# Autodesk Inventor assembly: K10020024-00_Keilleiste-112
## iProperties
Created: 2006-08
Part Number: K10020024-00_Keilleiste-112
Document SubType Name: Assembly
Designer: Kitscha
SBm.TeileNr: K10020024
SBm.TeileRev: 00
SBm.Rohteil: -
SBm.Werkstoff: -
SBm.WerkstNr: -
SBm.Gewicht: 0.0
SBm.BenennD: Keilleiste - 112
SBm.BenennE: tapered gib
SBm.AenIndex1: 0.0
SBm.AenDatum1: 2006-03-31
SBm.AenName1: -
SBm.AenIndex2: 0.0
SBm.AenDatum2: 2006-03-31
SBm.AenName2: -
SBm.InvVersion: 10.0
SBm.EntstAus: -
SBm.ZchgFormat: -
Author: Kitscha
